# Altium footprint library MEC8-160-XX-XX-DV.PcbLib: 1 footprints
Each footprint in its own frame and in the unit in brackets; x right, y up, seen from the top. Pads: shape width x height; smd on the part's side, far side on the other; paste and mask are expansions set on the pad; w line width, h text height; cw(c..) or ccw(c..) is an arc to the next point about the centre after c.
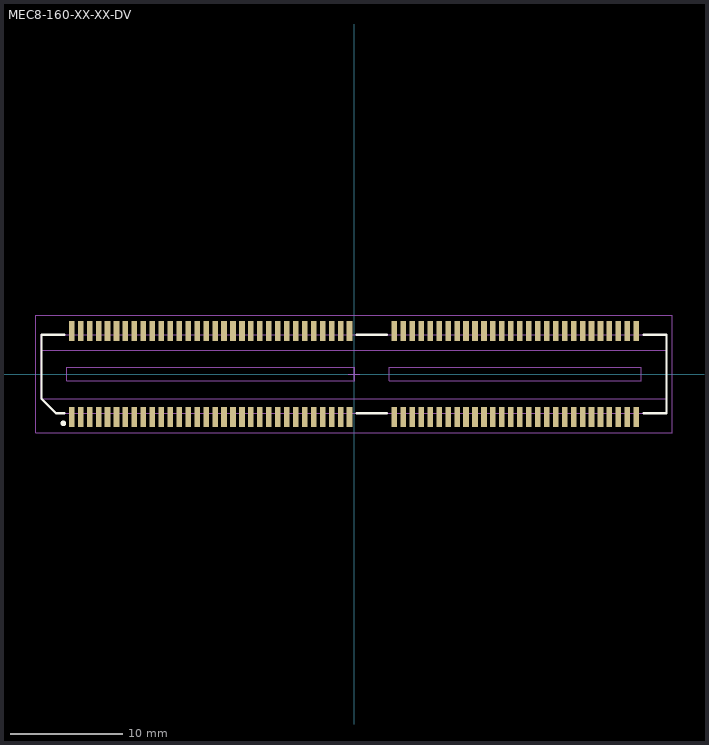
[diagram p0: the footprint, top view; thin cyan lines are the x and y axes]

## MEC8-160-XX-XX-DV [mm] "0.80mm pitch, 120 pin, mini edge-card assembly; vertical, double row"
height 8.65
pads (120):
  rect 0.5x1.8 smd mask+0: 1(-25.2,-3.85) 2(-25.2,3.85) 3(-24.4,-3.85) 4(-24.4,3.85) 5(-23.6,-3.85) 6(-23.6,3.85) 7(-22.8,-3.85) 8(-22.8,3.85) 9(-22,-3.85) 10(-22,3.85) 11(-21.2,-3.85) 12(-21.2,3.85) 13(-20.4,-3.85) 14(-20.4,3.85) 15(-19.6,-3.85) 16(-19.6,3.85) 17(-18.8,-3.85) 18(-18.8,3.85) 19(-18,-3.85) 20(-18,3.85) 21(-17.2,-3.85) 22(-17.2,3.85) 23(-16.4,-3.85) 24(-16.4,3.85) 25(-15.6,-3.85) 26(-15.6,3.85) 27(-14.8,-3.85) 28(-14.8,3.85) 29(-14,-3.85) 30(-14,3.85) 31(-13.2,-3.85) 32(-13.2,3.85) 33(-12.4,-3.85) 34(-12.4,3.85) 35(-11.6,-3.85) 36(-11.6,3.85) 37(-10.8,-3.85) 38(-10.8,3.85) 39(-10,-3.85) 40(-10,3.85) 41(-9.2,-3.85) 42(-9.2,3.85) 43(-8.4,-3.85) 44(-8.4,3.85) 45(-7.6,-3.85) 46(-7.6,3.85) 47(-6.8,-3.85) 48(-6.8,3.85) 49(-6,-3.85) 50(-6,3.85) 51(-5.2,-3.85) 52(-5.2,3.85) 53(-4.4,-3.85) 54(-4.4,3.85) 55(-3.6,-3.85) 56(-3.6,3.85) 57(-2.8,-3.85) 58(-2.8,3.85) 59(-2,-3.85) 60(-2,3.85) 61(-1.2,-3.85) 62(-1.2,3.85) 63(-0.4,-3.85) 64(-0.4,3.85) 65(3.6,-3.85) 66(3.6,3.85) 67(4.4,-3.85) 68(4.4,3.85) 69(5.2,-3.85) 70(5.2,3.85) 71(6,-3.85) 72(6,3.85) 73(6.8,-3.85) 74(6.8,3.85) 75(7.6,-3.85) 76(7.6,3.85) 77(8.4,-3.85) 78(8.4,3.85) 79(9.2,-3.85) 80(9.2,3.85) 81(10,-3.85) 82(10,3.85) 83(10.8,-3.85) 84(10.8,3.85) 85(11.6,-3.85) 86(11.6,3.85) 87(12.4,-3.85) 88(12.4,3.85) 89(13.2,-3.85) 90(13.2,3.85) 91(14,-3.85) 92(14,3.85) 93(14.8,-3.85) 94(14.8,3.85) 95(15.6,-3.85) 96(15.6,3.85) 97(16.4,-3.85) 98(16.4,3.85) 99(17.2,-3.85) 100(17.2,3.85) 101(18,-3.85) 102(18,3.85) 103(18.8,-3.85) 104(18.8,3.85) 105(19.6,-3.85) 106(19.6,3.85) 107(20.4,-3.85) 108(20.4,3.85) 109(21.2,-3.85) 110(21.2,3.85) 111(22,-3.85) 112(22,3.85) 113(22.8,-3.85) 114(22.8,3.85) 115(23.6,-3.85) 116(23.6,3.85) 117(24.4,-3.85) 118(24.4,3.85) 119(25.2,-3.85) 120(25.2,3.85)
Top Overlay:
  circle w0.25: c-25.95,-4.4 r0.125
  lines w0.2: -25.85,-3.5 -26.6,-3.5 -27.9,-2.2 -27.9,3.5 -25.85,3.5 ; 0.25,-3.5 2.95,-3.5 ; 0.25,3.5 2.95,3.5 ; 25.85,-3.5 27.9,-3.5 27.9,3.5 25.85,3.5
Mechanical 12:
  lines w0.001: -27.9,-2.2 -26.6,-3.5 27.9,-3.5 27.9,3.5 -27.9,3.5 -27.9,-2.2
Mechanical 13:
  lines w0.1: -27.9,2.1 27.9,2.1 ; 27.9,-2.2 -27.9,-2.2 ; -27.9,-2.2 -26.6,-3.5 27.9,-3.5 27.9,3.5 -27.9,3.5 -27.9,-2.2 ; -25.65,-0.6 0.05,-0.6 0.05,0.6 -25.65,0.6 -25.65,-0.6 ; 3.15,-0.6 25.65,-0.6 25.65,0.6 3.15,0.6 3.15,-0.6
  text ".Designator" at 0.254,0.254 h1.52
Mechanical 15:
  lines w0.05: -0.5,0 0.5,0 ; 0,-0.5 0,0.5 ; -28.4,-5.25 28.4,-5.25 28.4,5.25 -28.4,5.25 -28.4,-5.25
